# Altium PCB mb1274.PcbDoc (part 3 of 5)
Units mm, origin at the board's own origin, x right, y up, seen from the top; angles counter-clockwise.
Board outline 70 x 105 mm, 4 copper layers (Top Layer, Mid-Layer 1, Mid-Layer 2, Bottom Layer), stack 1.58 mm thick; 329 components, 271 nets, 1213 pads, 779 vias.
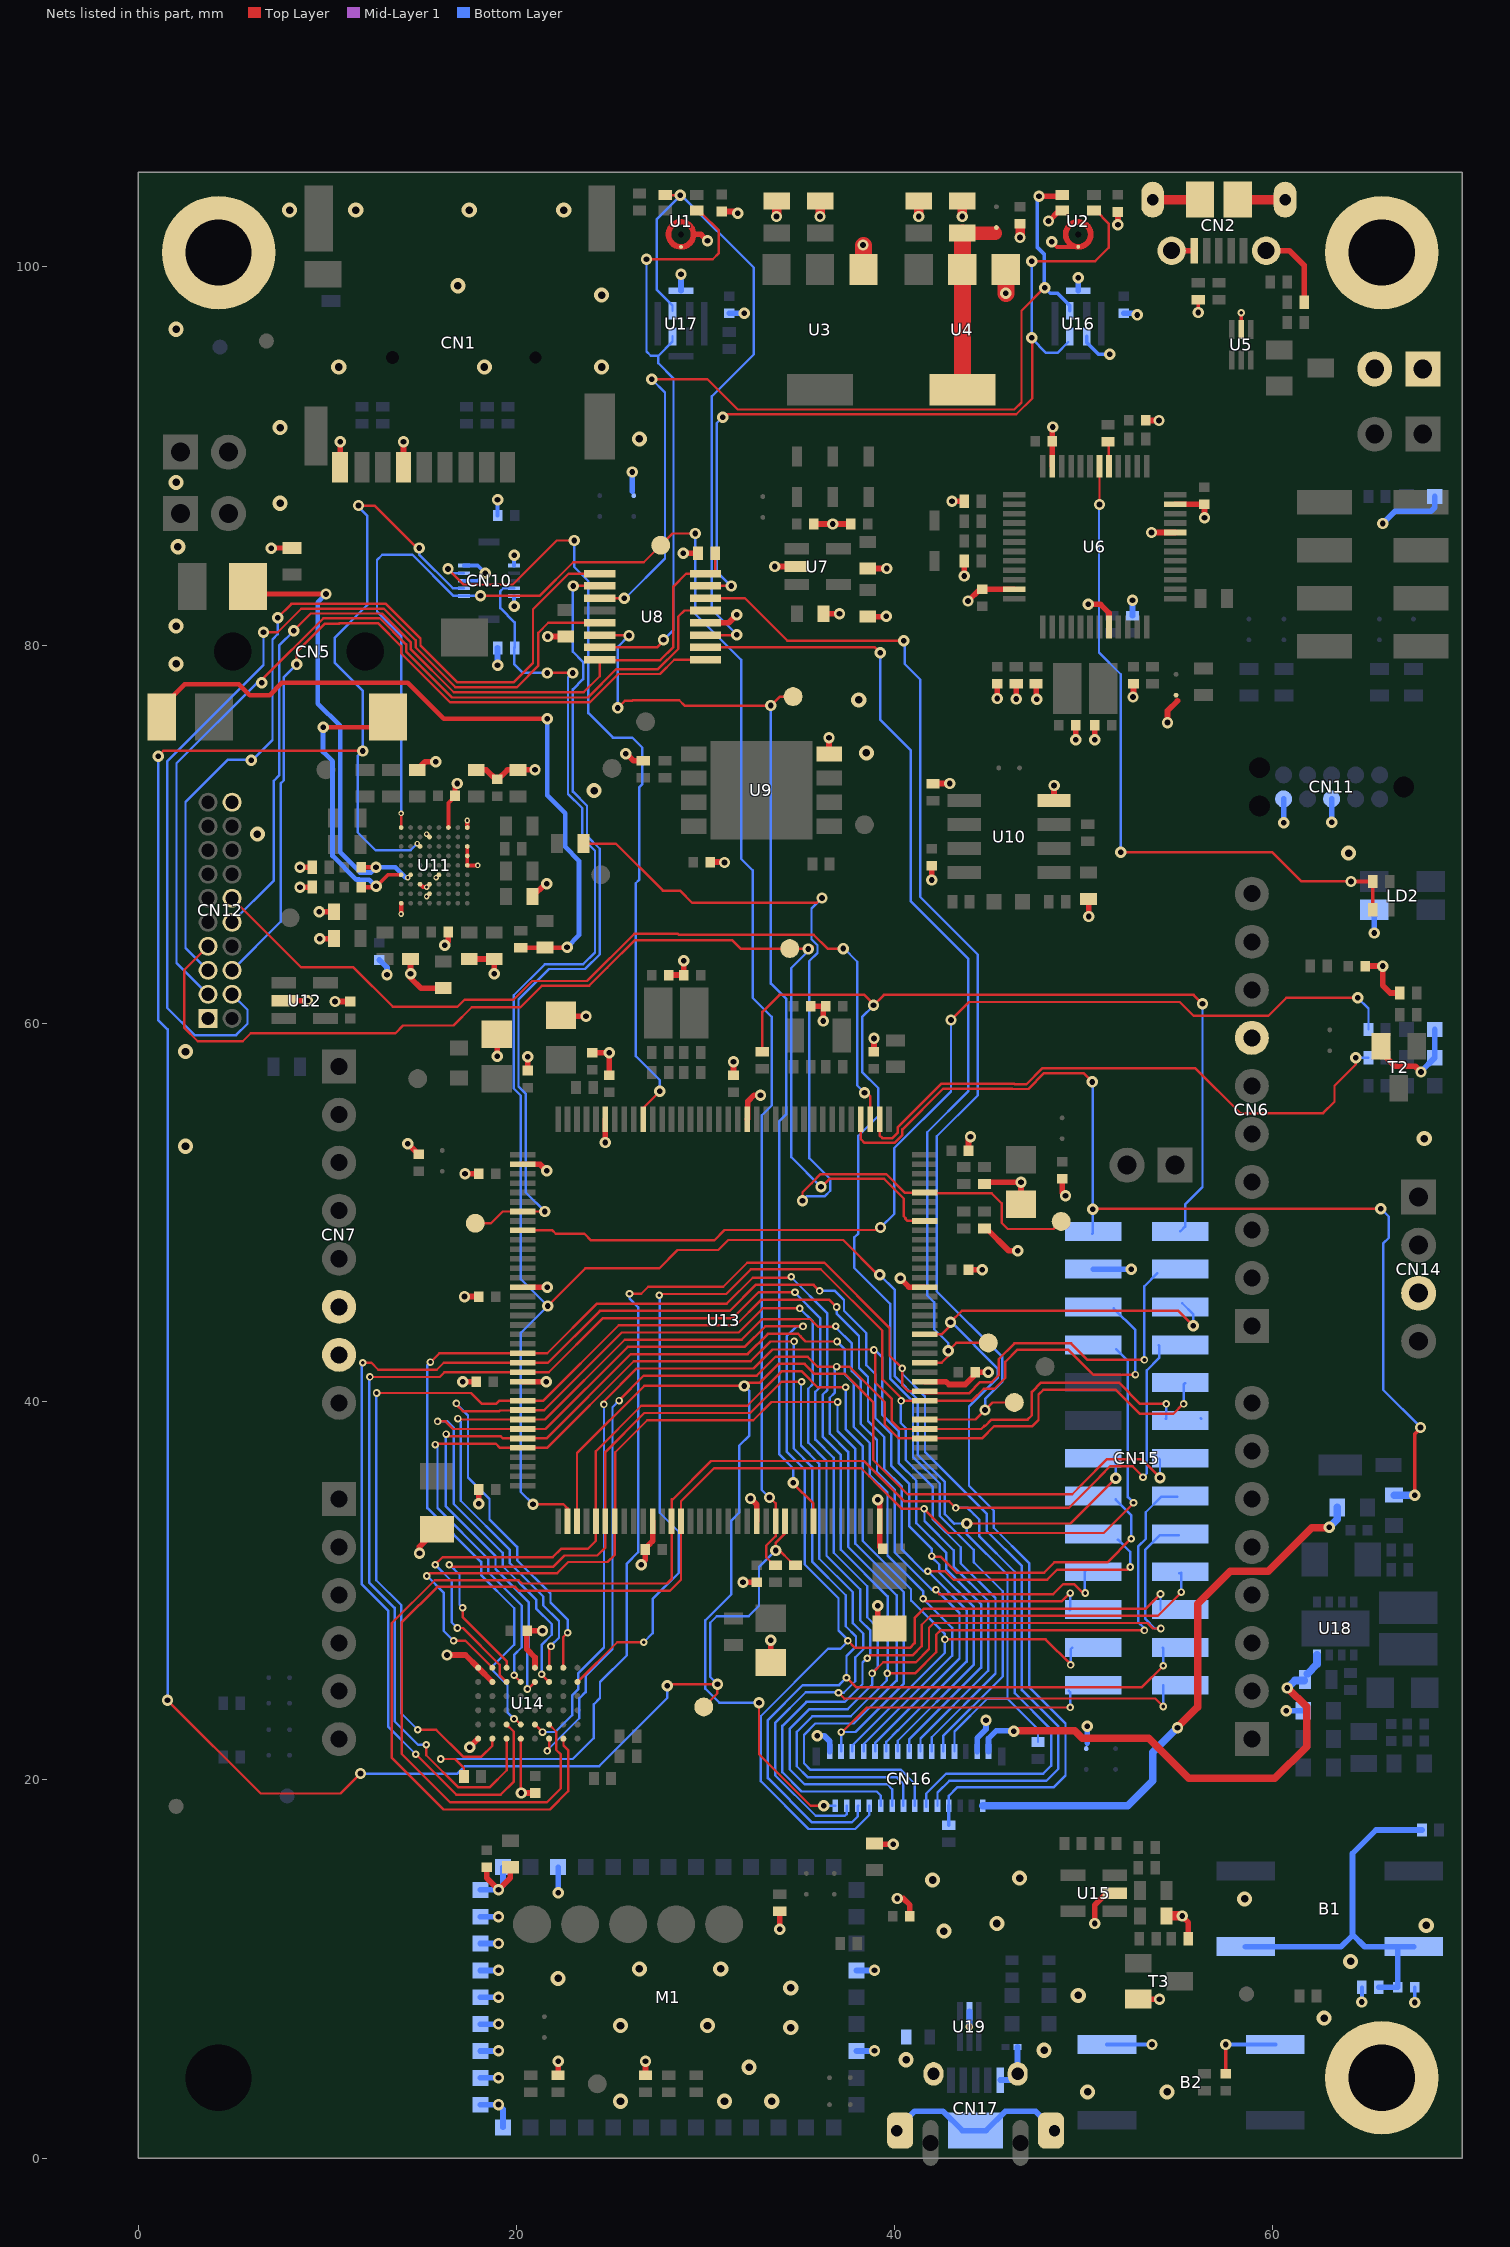
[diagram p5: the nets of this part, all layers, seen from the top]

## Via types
v1: diameter 0.6, hole 0.3, Top Layer to Bottom Layer, tented both sides, 574 vias
v2: diameter 0.4, hole 0.2, Top Layer to Bottom Layer, tented both sides, 125 vias
v3: diameter 0.8, hole 0.4, Top Layer to Bottom Layer, tented both sides, 49 vias
v4: diameter 0.3, hole 0.15, Top Layer to Bottom Layer, tented both sides, 31 vias

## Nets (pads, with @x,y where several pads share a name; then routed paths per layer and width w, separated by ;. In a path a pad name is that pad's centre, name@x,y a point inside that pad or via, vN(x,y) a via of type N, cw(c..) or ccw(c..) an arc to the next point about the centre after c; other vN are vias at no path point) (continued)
CODEC_WS: R28.1 TP11.1 U13.140 | length 48.8
  Top Layer w0.127: R28.1@23.55,69.5 25.25,69.5 27.738,67.012 28.644,67.012 29.279,66.377 35.877,66.377 v1@36.15,66.65 ; v1(35.125,50.625) v1@35.137,50.637 ; v1@35.125,50.65 35.125,51.064 35.609,51.549 35.609,51.553 36.08,52.024 39.548,52.024 40.522,51.05 U13.140@41.575,51.05 41.575,51.01 45.125,51.01 45.65,50.484 45.65,49.45 45.975,49.125 48.4,49.125 TP11.1@48.8,49.525
  Bottom Layer w0.127: v1@35.3,50.625 v1(35.125,50.625) 35.36,50.859 36.303,50.859 36.59,51.147 36.59,51.76 35.481,52.869 35.481,63.287 35.915,63.722 35.915,64.128 35.6,64.444 35.6,66.075 v1(36.15,66.625)
CTP_INT: CN10.2 U13.27 | length 42.6
  Top Layer w0.127: v1(16.375,84.025) 17.2,83.2 19.8,83.2 22.125,85.525 v1(23.05,85.525) ; U13.27@26.7,54.925 26.7,55.525 v1(27.575,56.4)
  Bottom Layer w0.127: v1(16.375,84.025) 16.6,83.8 CN10.2@17.225,83.8 ; v1(23.05,85.525) 23.05,84.125 23.8,83.375 23.8,76.4 25.096,75.104 26.121,75.104 26.654,74.571 26.654,72.645 26.5,72.491 26.5,67.575 ; 26.475,67.575 26.308,67.408 26.308,58.267 27.575,57 v1(27.575,56.4)
DETECTN: CN12.10 R13.2 U8.8 U8.16 | length 46.8
  Top Layer w0.127: v1(8.225,80.75) 8.225,80.767 9.125,81.667 12.89,81.667 14.417,80.14 14.417,79.765 16.682,77.5 23.55,77.5 24.4,78.35 U8.16@24.4,79.225 ; U8.16@24.525,79.2 27.6,79.2 28.296,79.896 28.296,83.096 28.975,83.775 U8.8@30,83.775 ; U8.8@30.45,83.775 30.5,83.825 R13.2@30.5,84.85
  Bottom Layer w0.127: CN12.10@4.96,65.34 7.175,67.555 7.175,72.825 7.45,73.1 7.45,79.975 v1(8.225,80.75)
DFSDM1_CKOUT: TP2.1 U8.14 U13.100 | length 59.7
  Top Layer w0.127: U8.14@24.4,80.525 25.925,80.525 v1(25.95,80.5) ; v1(25.35,76.675) 25.725,77.05 26.116,77.05 26.145,77.079 28.605,77.079 28.884,76.8 v1(33.45,76.8) 33.925,77.275 TP2.1@34.625,77.275 ; v1@34.625,35.675 35.7,34.6 U13.100@35.7,33.675
  Bottom Layer w0.127: v1(25.35,76.675) 25.35,79.9 v1(25.95,80.5) ; v1@33.45,76.75 33.45,62.1 34.271,61.279 34.271,55.196 33.9,54.825 33.9,37.2 34.625,36.475 v1(34.625,35.7)
DFSDM1_DATIN1: TP13.1 U8.2 U13.122 | length 53.8
  Top Layer w0.127: U8.2@30,79.875 38.95,79.875 v1(39.225,79.6) ; U13.122@41.575,42.05 42.3,42.05 42.475,42.05 42.827,42.402 v1(42.827,42.677) 43.25,43.1 TP13.1@44.95,43.1
  Bottom Layer w0.127: v1(39.225,79.6) 39.225,76.067 40.842,74.45 40.842,66.465 43.88,63.427 43.88,56.398 41.717,54.235 41.717,45.615 42.091,45.24 42.091,43.824 42.827,43.089 v1(42.827,42.677) 42.925,42.579 42.925,42.55 v1@42.813,42.662
DFSDM2_CKOUT: TP15.1 U8.6 U13.116 | length 61.6
  Top Layer w0.127: U8.6@30,82.475 32.075,82.475 34.326,80.225 v1(40.475,80.225) ; U13.116@41.575,39.05 44.275,39.05 v1(44.775,39.55) 45.175,39.95 TP15.1@46.325,39.95
  Bottom Layer w0.127: v1(40.475,80.225) 40.525,80.225 40.525,79 41.35,78.175 41.35,66.675 44.388,63.637 44.388,56.188 42.225,54.025 42.225,45.825 45.694,42.356 45.694,41.051 44.775,40.132 v1(44.775,39.55)
DFSDM2_DATIN1: TP12.1 U8.10 U13.43 | length 42.9
  Top Layer w0.127: TP12.1@17.825,49.425 18.65,49.425 19.275,50.05 U13.43@20.325,50.05 v1(21.5,50.05) ; v1(23,83.125) U8.10@24.4,83.125
  Bottom Layer w0.127: v1(21.5,50.05) 20.483,51.067 20.483,56.285 20.108,56.66 20.108,61.258 21.721,62.871 23.63,62.871 24.404,63.645 24.404,69.23 23.729,69.905 23.729,71.5 22.979,72.25 22.979,77.654 23.525,78.2 23.525,79.1 22.975,79.65 v1@22.975,83.1
DFSDM2_DATIN7: CN12.7 TP9.1 U13.137 | length 61.5
  Top Layer w0.127: CN12.7@3.69,64.07 2.425,62.805 2.425,59.775 3.15,59.05 5.525,59.05 5.95,59.475 13.6,59.475 14.008,59.883 16.665,59.883 17.632,60.85 20.207,60.85 21.34,61.983 23.842,61.983 24.801,62.942 ; 24.808,62.942 24.801,62.942 ; v1(35.425,63.925) 35.4,63.95 TP9.1@34.45,63.95 31.85,63.95 31.417,64.383 26.242,64.383 24.801,62.942 ; v1@35.425,63.95 35.575,63.95 v1@35.675,64.05 ; v1@36.125,51.35 36.545,51.77 39.443,51.77 40.475,50.738 40.475,49.8 40.575,49.7 ; 40.55,49.675 40.675,49.55 U13.137@41.575,49.55
  Bottom Layer w0.127: v1(35.425,63.925) 35.425,63.825 34.525,62.925 34.525,52.925 v1(36.1,51.35)
DMIC1_DFSDM1_CKOUT: U1.4 U8.15 U17.3 | length 32.8
  Top Layer w0.127: U8.15@24.4,79.875 27.425,79.875 27.775,80.225 v1(27.775,80.275) ; v1(26.875,100.4) 30.375,100.4 30.7,100.725 30.7,101.925 U1.4@29.825,102.8 ; U1.4@29.538,102.967 U1.4@29.765,102.74
  Bottom Layer w0.127: v1(26.875,100.4) 26.875,95.525 27.1,95.3 27.5,95.3 ; v1(27.775,80.275) 28.3,80.8 28.3,94.1 27.5,94.9 27.5,95.3 ; U17.3@28.25,96.325 28.25,96.05 27.5,95.3
DMIC1_DFSDM1_DATIN1: U1.1 U8.3 U17.4 | length 35.7
  Top Layer w0.127: U1.1@27.862,103.789 28.636,103.789 v1(28.65,103.775) ; U8.3@30,80.525 31.625,80.525 v1(31.65,80.55)
  Bottom Layer w0.127: U17.4@28.25,97.675 28.25,97.95 27.425,98.775 27.425,102.525 v1@28.675,103.775 ; v1@28.725,103.775 32.55,99.95 32.55,95.375 30.325,93.15 30.325,81.875 v1(31.65,80.55)
DMIC2_DFSDM2_CKOUT: U2.4 U8.7 U16.3 | length 44
  Top Layer w0.127: U8.7@30,83.125 v1(31.35,83.125) ; v1@30.925,92.025 31.1,92.2 46.427,92.2 47.275,93.048 v1@47.275,96.2 ; v1(47.25,100.3) 50.6,100.3 51.31,101.01 51.31,102.29 50.633,102.967 U2.4@50.538,102.967
  Bottom Layer w0.12: 48,95.45 48.6,95.45
  Bottom Layer w0.127: v1(30.9,92.05) 30.579,91.729 30.579,83.896 v1(31.35,83.125) ; v1@30.912,92.037 v1@30.95,92.075 ; v1(47.25,100.3) v1(47.25,96.25) 47.25,96.2 48,95.45 ; 48.6,95.45 U16.3@49.175,96.025
DMIC2_DFSDM2_DATIN1: U2.1 U8.11 U16.4 | length 49.4
  Top Layer w0.127: U8.11@24.4,82.475 v1@25.7,82.475 ; v1(27.15,94.05) 30.1,94.05 31.696,92.454 46.322,92.454 46.7,92.832 46.7,97.675 v1@47.9,98.875 ; v1@47.913,98.862 47.925,98.875 v1(47.925,98.9)
  Top Layer w0.3: v1(47.627,103.73) 47.632,103.725 48.798,103.725 U2.1@48.862,103.789
  Bottom Layer w0.127: v1(25.7,82.475) 25.75,82.475 27.85,84.575 27.85,93.35 v1(27.15,94.05)
  Bottom Layer w0.2: v1@47.53,103.73 47.53,101.045 47.9,100.675 47.9,98.925 v1(47.925,98.9) 48.225,98.6 48.6,98.6 49.25,97.95 U16.4@49.25,97.675
  Bottom Layer w0.3: v1@47.53,103.73 v1(47.627,103.73)
EXT_DFSDM1_CKOUT: CN12.4 U8.13 | length 51.6
  Top Layer w0.127: v1(6.625,80.675) 7.375,80.675 8.621,81.921 12.995,81.921 14.671,80.245 14.671,79.87 16.77,77.771 20.021,77.771 21.16,78.909 21.16,80.653 21.681,81.175 U8.13@24.4,81.175
  Bottom Layer w0.127: CN12.4@4.96,61.53 5.775,60.715 5.775,59.975 5.175,59.375 2.975,59.375 1.525,60.825 1.525,73.85 6.625,78.95 v1(6.625,80.675)
EXT_DFSDM1_DATIN1: CN12.6 U8.1 | length 43.4
  Top Layer w0.127: v1(8.375,78.975) 8.375,79.641 9.851,81.116 10.607,81.116 10.65,81.159 12.679,81.159 13.909,79.929 13.909,79.554 16.492,76.971 23.88,76.971 25.38,78.471 27.589,78.471 28.343,79.225 U8.1@30,79.225
  Bottom Layer w0.127: CN12.6@4.96,62.8 7.525,65.365 7.525,72.675 7.704,72.854 7.704,78.304 v1(8.375,78.975)
EXT_DFSDM2_CKOUT: CN12.3 U8.5 | length 49
  Top Layer w0.127: v1(6.525,78) 6.525,78.15 9.788,81.413 12.784,81.413 14.163,80.034 14.163,79.659 16.597,77.225 23.775,77.225 25.275,78.725 27.484,78.725 28.55,79.791 28.55,81.5 28.875,81.825 U8.5@30,81.825
  Bottom Layer w0.127: CN12.3@3.69,61.53 2.025,63.195 2.025,73.75 6.275,78 v1(6.525,78)
EXT_DFSDM2_DATIN1: CN12.5 U8.9 | length 45.2
  Top Layer w0.127: v1(7.375,81.45) 8.1,82.175 13.1,82.175 14.925,80.35 14.925,79.975 16.875,78.025 19.85,78.025 20.875,79.05 20.875,81.891 22.759,83.775 U8.9@24.4,83.775
  Bottom Layer w0.127: CN12.5@3.69,62.8 2.5,63.99 2.5,71.7 4.725,73.925 5.95,73.925 v1(5.975,73.9) ; v1@6.05,73.925 7.1,74.975 7.1,80.3 7.375,80.575 v1(7.375,81.45)
GND: B2.3 B2.4 C1.1 C2.1 C3.1 C4.1 C5.1 C6.1 C7.1 C8.1 C9.1 C10.1 C11.1 C12.1 C13.1 C14.1 C15.1 C16.1 C17.1 C18.1 C19.1 C20.2 C21.2 C22.1 C23.1 C24.1 C25.1 C26.1 C27.1 C28.1 C30.1 C32.1 C33.2 C35.1 C37.1 C38.1 C39.1 C40.2 C41.1 C42.1 C43.2 C44.2 C45.1 C46.2 C47.2 C48.2 C49.2 C50.1 C51.1 C52.1 C53.1 C54.1 C55.2 C56.1 C57.1 C58.1 C59.1 C60.1 C61.1 C62.1 C63.1 C64.1 C65.1 C66.1 C67.1 C68.1 C69.1 C70.2 C71.1 C72.1 C73.2 C74.2 C75.1 C76.1 C77.2 C78.1 C79.1 C80.1 C81.2 C82.1 C90.1 CN1.6 CN1.9 CN2.5 CN2.6 CN2.7 CN2.8 CN2.9 CN2.10 CN2.11 CN6.7 CN7.6 CN7.7 CN10.1 CN10.3 CN10.6 CN10.10 CN11.3 CN11.5 CN12.1 CN12.20 CN14.3 CN15.4 CN16.1 CN16.27 CN17.5 CN17.6 CN17.7 CN17.8 CN17.9 CN17.10 H1.1 H2.1 H4.1 JP1.1 JP1.2 L5.1 LD2.1 LD3.2 LD4.2 LD6.2 M1.1 M1.3 M1.17 M1.20 M1.35 M1.36 M1.37 M1.38 M1.39 M1.40 M1.41 M1.42 M1.43 M1.44 R3.1 R5.1 R9.1 R12.2 R13.1 R14.1 R16.2 R17.2 R20.2 R24.1 R32.1 R35.1 R41.1 R53.1 R55.1 R68.1 R70.1 R75.2 R76.2 R86.1 R88.1 R109.1 SB3.1 SB13.1 SB23.1 T2.2 T3.2 U1.3 U2.2 U2.3 U3.1 U4.1 U5.2 U6.8 U6.20 U6.23 U6.35 U6.47 U7.2 U8.4 U9.4 U10.4 U11.A1 U11.A3 U11.A4 U11.A5 U11.C1 U11.D6 U11.E2 U11.E7 U11.E8 U11.F7 U11.H9 U12.2 U13.16 U13.31 U13.38 U13.51 U13.61 U13.83 U13.94 U13.107 U13.120 U13.130 U14.D1 U14.E6 U14.G2 U14.H1 U14.H6 U15.2 U16.2 U16.5 U17.5 U19.2 U20.2 U21.2 | length 226
  Top Layer w0.127: v4(15.75,67.7) U11.D6@15.895,67.845 ; v4@15.766,67.715 v4@15.777,67.726 ; v4@15.766,67.716 U11.D6@15.9,67.85 ; v1@20.225,19.35 U14.E6@20.225,22.175 ; v1(33.918,12.095) v1@33.925,12.102 ; v1@39.822,16.6 v1(39.925,16.6)
  Top Layer w0.2: U11.F7@14.9,67.35 15.05,67.2 v4(15.25,67.2) U11.E7@15.4,67.35 ; v4(15.25,66.7) U11.E8@15.4,66.85 ; v4(15.25,70) U11.E2@15.4,69.85 ; U11.C1@16.4,70.35 16.4,71.65 C26.1@16.75,72 ; U11.A3@17.4,69.35 U11.A4@17.4,68.85 U11.A5@17.4,68.35 v4(17.95,68.35) ; v1(48.3,101.325) 48.573,101.052 U2.3@49.7,101.052 ; R3.1@56.05,98.25 56.05,97.582 v1(56.053,97.58) ; C78.1@57.5,4.45 v1(57.5,6) ; U5.2@58.325,96.68 v2(58.325,97.575)
  Top Layer w0.25: v1(7.025,85.125) R12.2@8.125,85.125 ; v4(13.9,65.775) U11.H9@13.9,66.35 ; C26.1@16.75,72.025 16.75,72.6 16.829,72.679 v1(16.876,72.679) ; U11.A1@17.4,70.35 v4(17.4,70.725)
  Top Layer w0.3: U12.2@7.7,61.2 v1(8.95,61.2) ; v1(8.55,67.2) R35.1@9.2,67.2 ; v1(8.55,68.25) R32.1@9.2,68.25 ; v1(9.575,65.9) C33.2@10.35,65.9 ; v1(9.6,64.475) C40.2@10.35,64.475 ; v1(10.4,61.15) C45.1@11.2,61.15 ; CN1.9@10.675,89.4 v1(10.675,90.75) ; CN1.6@14.025,89.4 v1(14.025,90.75) ; v1@14.3,53.6 C57.1@14.825,53.075 ; C37.1@14.4,63.4 v1(14.4,62.625) 14.4,62.4 14.95,61.85 15.925,61.85 15.95,61.875 C41.1@16.125,61.875 ; C22.1@14.75,73.4 15.175,73.825 v1@15.7,73.825 ; v1(14.875,31.975) 14.875,32.325 C64.1@15.8,33.25 ; v1(16.2,64.125) 16.4,64.325 C35.1@16.4,64.825 ; v1(16.325,26.6) 17.3,26.6 U14.H1@17.975,25.925 U14.G2@18.725,25.175 ; v1(17.15,41.05) C63.1@17.875,41.05 ; v1(17.25,45.55) C61.1@18,45.55 ; v1(17.275,52.05) C59.1@18,52.05 ; C38.1@17.5,63.4 C39.1@18.825,63.4 ; v1(17.525,21.725) U14.H6@17.975,22.175 ; C23.1@17.875,73.4 18.4,73.4 C25.1@18.9,72.9 ; v1(18,34.6) C65.1@18,35.35 ; C75.1@18.425,15.375 18.425,14.807 v1(19.045,14.187) 19.675,14.817 C73.2@19.675,15.375 ; v1(18.825,62.625) C39.1@18.825,63.4 ; C39.1@18.85,63.375 C39.1@18.825,63.4 ; C49.2@18.95,59.425 18.975,59.4 v1(18.975,58.25) ; C25.1@18.975,72.9 19.025,72.9 19.525,73.4 C24.1@20.075,73.4 v1(20.975,73.4) ; v1@20.225,19.35 v1@20.275,19.3 ; v1(20.25,19.3) v1@20.275,19.3 ; U13.61@20.325,41.05 v1(21.575,41.05) ; U13.51@20.325,46.05 v1(21.625,46.05) ; U13.38@20.325,52.55 21.25,52.55 v1(21.6,52.2) ; C71.1@20.55,27.85 20.55,26.9 20.975,26.475 U14.D1@20.975,25.925 ; C71.1@20.575,27.875 v1(21.375,27.875) ; C52.1@20.6,57.5 v1(20.6,58.225) ; C32.1@20.85,66.7 21.525,67.375 v1(21.6,67.375) ; C72.1@21,19.3 v1@20.275,19.3 ; v1(21.65,80.45) C16.1@22.6,80.45 ; R75.2@22.2,4.375 v1(22.2,5.125) ; C48.2@22.35,60.425 22.4,60.375 v1(23.675,60.375) ; C51.1@24,58.45 v1(24.9,58.45) ; v1(24.7,53.7) U13.31@24.7,54.925 ; v1@24.875,58.4 24.9,58.375 C53.1@24.9,57.25 ; v1(25.775,74.25) 25.85,74.25 25.837,74.238 26.2,73.875 R20.2@26.7,73.875 ; v1@26.675,31.5 26.8,31.625 C67.1@26.8,32.175 26.8,32.234 27.2,32.634 27.2,32.8 ; R76.2@26.825,4.375 v1(26.825,5.125) ; C67.1@27,32.425 27.2,32.625 U13.83@27.2,33.675 ; C43.2@28.05,62.55 28.825,62.55 C44.2@28.85,62.525 ; v1(28.825,84.85) R13.1@29.6,84.85 ; C44.2@28.85,62.55 v1(28.85,63.3) ; 29.363,101.715 29.76,101.715 v1(30.1,101.375) ; U8.4@30,81.175 31.225,81.175 v1(31.65,81.6) ; C28.1@30.25,68.525 31,68.525 v1(31,68.5) ; C1.1@30.85,102.925 31.7,102.925 v1(31.7,102.825) ; C54.1@31.475,57.25 v1(31.475,57.975) ; v1(31.975,30.45) C68.1@32.7,30.45 ; U13.16@32.2,54.925 32.232,54.957 32.232,55.877 32.558,56.202 v1(32.902,56.202) ; v1(32.375,34.875) 32.7,34.55 U13.94@32.7,33.675 ; C70.2@33.45,26.2 33.45,27.374 v1(33.452,27.376) ; v1(33.65,84.15) U7.2@34.825,84.15 ; v1@33.75,102.657 v1(33.752,102.655) ; v1@33.925,12.102 R68.1@33.925,13.05 ; C46.2@35.55,60.9 36.275,60.9 C47.2@36.3,60.925 ; C11.1@35.725,86.4 36.675,86.4 v1@36.7,86.425 ; v1@36.05,102.657 v1(36.052,102.655) ; v1(36.225,60.125) 36.225,60.775 C47.2@36.35,60.9 ; C17.1@36.225,81.65 v1(37.075,81.65) ; U9.4@36.525,74.23 v1(36.525,75.1) ; v1(36.725,86.4) C12.1@37.675,86.4 ; v1(38.325,101.15) v1@38.35,101.125 ; C14.1@38.575,81.5 39.525,81.5 v1(39.55,81.525) ; C13.1@38.575,84.05 v1(39.575,84.05) ; C74.2@38.874,16.6 v1@39.822,16.6 ; C50.1@38.9,58.5 v1(38.9,59.2) ; v1(39.1,29.2) 39.1,28.625 C69.1@39.725,28 ; v1(39.1,34.8) 39.2,34.7 U13.107@39.2,33.675 39.2,32.325 C66.1@39.275,32.25 ; v1(40.125,13.725) 40.45,13.725 40.8,13.375 C77.2@40.8,12.775 ; v1(40.3,46.525) 40.275,46.525 40.75,46.05 U13.130@41.575,46.05 ; v1@41.275,102.65 41.277,102.652 v1(41.277,102.655) ; U13.120@41.575,41.05 42.711,41.05 42.863,40.899 43.725,40.899 44.175,41.349 C62.1@44.175,41.375 ; v1(41.95,67.575) C27.1@41.95,68.325 ; R24.1@42.025,72.675 v1(42.9,72.675) ; v1(43.025,87.6) R9.1@43.675,87.6 ; v1@43.575,102.65 v1(43.577,102.655) v1(43.577,102.655) ; v1(43.675,83.65) R14.1@43.675,84.45 ; v1(43.875,82.325) 44.5,82.95 C15.1@44.625,82.95 ; C60.1@43.9,46.975 v1(44.625,46.975) ; C56.1@43.9,53.25 43.9,53.95 43.952,54.002 v1(44.002,54.002) ; C62.1@44.25,41.55 v1(44.95,41.55) ; C15.1@44.6,82.925 C15.1@44.625,82.95 ; R55.1@44.75,49.15 44.85,49.15 46.025,47.975 v1(46.5,47.975) ; R53.1@44.75,51.5 44.85,51.6 v1@46.675,51.6 ; v1(45.425,77.175) C19.1@45.425,77.95 ; U6.47@46.325,82.95 C15.1@44.625,82.95 ; v1(46.425,77.15) R16.2@46.425,77.95 ; C55.2@46.675,50.425 v1@46.675,51.6 ; v1(46.677,51.602) v1@46.675,51.6 ; R17.2@47.475,77.95 47.475,77.15 v1(47.5,77.125) ; v1@48.125,102.4 48.692,102.967 U2.2@48.862,102.967 ; U6.35@48.325,89.45 48.325,90.725 C9.1@48.35,90.75 ; C9.1@48.325,90.775 48.325,91.5 v1(48.35,91.525) ; U10.4@48.425,71.78 v1(48.425,72.575) ; C58.1@48.85,51.775 48.85,51.025 49,50.875 v1(49.025,50.875) ; v1(49.575,75) C20.2@49.575,75.75 ; v1(50.225,82.15) 50.875,82.15 51.325,81.7 U6.8@51.325,80.95 ; v1(50.25,65.65) C30.1@50.25,66.575 ; v1(50.575,12.4) 50.575,13.35 ; 50.575,13.375 51.2,14 U15.2@51.625,14 ; v1(50.575,75) C21.2@50.575,75.75 ; U15.2@51.133,13.9 U15.2@51.15,13.9 ; v1(51.8,102.225) C2.1@51.8,102.9 ; v1(52.6,77.25) 52.625,77.225 C18.1@52.625,77.95 ; v1(52.828,97.455) v1@52.828,97.553 ; T3.2@52.875,8.4 v1(54,8.4) ; C8.1@53.275,91.875 v1(53.975,91.875) ; v1(53.575,85.95) U6.20@54.825,85.95 ; v1(54.425,75.9) 54.425,76.525 54.95,77.05 ; CN2.7@54.475,100.9 54.525,100.85 CN2.7@54.64,100.85 CN2.5@55.84,100.85 ; U6.23@54.825,87.45 56.35,87.45 C10.1@56.375,87.475 ; v1@55.2,12.775 55.525,12.45 R70.1@55.525,11.6 ; v1(56.375,86.725) C10.1@56.375,87.45 ; CN2.6@59.675,100.85 60.875,100.85 61.65,100.075 R5.1@61.65,98.125 ; C42.1@64.875,63.025 v1(65.8,63.025) 65.8,62 66.2,61.6 R41.1@66.7,61.6 ; T2.2@65.7,58.775 65.7,58.475 66.45,57.725 67.525,57.725 v1(67.825,57.425)
  Top Layer w0.5: v1@33.75,102.657 C3.1@33.75,103.475 ; v1@36.05,102.657 C4.1@36.05,103.475 ; v1@41.275,102.65 C5.1@41.275,103.475 ; v1(43.577,102.655) C6.1@43.575,103.475 ; v1(46.625,101.55) C7.1@46.625,102.275 ; CN2.8@53.675,103.55 CN2.11@56.14,103.55 ; C76.1@54.375,12.8 v1(55.2,12.8) ; CN2.10@58.14,103.55 CN2.9@60.6,103.55
  Top Layer w0.9: U3.1@38.35,99.85 v1@38.35,101.125 ; v1(45.875,98.6) U4.1@45.875,99.85
  Mid-Layer 1 w0.127: v4@15.715,67.664 v4@15.777,67.726
  Mid-Layer 1 w0.3: v1@32.825,56.279 v1(32.902,56.202) ; v1@33.752,102.577 v1(33.752,102.655) ; v1@36.052,102.577 v1(36.052,102.655) ; v1@43.577,102.554 v1(43.577,102.655) ; v1(56.375,86.725) v1@56.4,86.7
  Bottom Layer w0.127: v1@19.038,2.82 v1(19.045,2.827) ; v1@19.038,4.24 v1(19.045,4.247) ; v1@19.038,5.66 v1(19.045,5.667) ; v1@19.038,7.08 v1(19.045,7.087) ; v1@19.038,8.5 v1(19.045,8.507) ; v1@19.038,9.92 v1(19.045,9.927) ; v1@19.038,11.34 v1(19.045,11.347) ; v1@19.038,12.76 v1(19.045,12.767) ; v1@19.038,14.18 v1(19.045,14.187) ; v1@38.922,5.66 v1(38.929,5.667) ; v1@38.922,9.92 v1(38.929,9.927)
  Bottom Layer w0.2: CN10.3@17.225,83.4 17.95,83.4 v1(18.35,83.8) 17.95,84.2 CN10.1@17.225,84.2 ; C81.2@19,86.85 v1(19,87.675) ; v1(19.875,82.05) CN10.6@19.875,82.6 ; CN10.10@19.875,84.2 v1(19.875,84.75) ; U16.2@50.15,96.325 50.15,96 50.775,95.375 v1(51.375,95.375) ; B2.3@51.225,6 v1(53.6,6) ; v1(57.5,6) B2.4@60.125,6 ; v1(64.7,8.25) R109.1@64.7,9.025 ; v1(67.5,8.225) C90.1@67.5,9.025
  Bottom Layer w0.3: C82.1@12.75,63.35 13.15,62.95 v1(13.15,62.575) ; M1.36@18.09,2.82 v1@19.038,2.82 ; M1.37@18.09,4.24 v1@19.038,4.24 ; M1.38@18.09,5.66 v1@19.038,5.66 ; M1.39@18.09,7.08 v1@19.038,7.08 ; M1.40@18.09,8.5 v1@19.038,8.5 ; M1.41@18.09,9.92 v1@19.038,9.92 ; M1.42@18.09,11.34 v1@19.038,11.34 ; M1.43@18.09,12.76 v1@19.038,12.76 ; M1.44@18.09,14.18 v1@19.038,14.18 ; v1(19,78.925) R88.1@19,79.85 ; v1(19.045,2.827) 19.29,2.582 M1.35@19.29,1.62 ; v1(19.045,14.187) 19.29,14.432 M1.1@19.29,15.38 ; v1(22.2,14.025) 22.204,14.029 M1.3@22.204,15.38 ; 26.125,88.125 v1(26.125,89.15) ; U17.5@28.7,98.725 v1(28.7,99.6) ; C80.1@31.25,97.55 v1(32.05,97.55) ; v1@35.9,22.3 v1@35.925,22.325 ; v1(35.9,22.325) v1@35.925,22.325 ; CN16.1@36.56,21.5 36.56,22.04 36.275,22.325 v1@35.925,22.325 ; M1.20@37.974,5.66 v1@38.922,5.66 ; M1.17@37.974,9.92 v1@38.922,9.92 ; CN17.9@40.1,1.525 41.05,2.475 42.55,2.475 43.575,1.45 44.825,1.45 45.85,2.475 47.45,2.475 CN17.8@48.425,1.5 ; v2(43.95,6.95) U19.2@43.95,7.755 ; CN16.27@44.36,21.5 44.36,22.21 44.825,22.675 v1(44.825,23.15) ; CN17.5@45.575,4.125 46.175,4.125 CN17.6@46.487,4.438 ; U20.2@46.487,5.875 CN17.6@46.487,4.438 ; CN17.6@46.5,4.35 46.487,4.363 CN17.6@46.487,4.438 ; CN17.6@46.5,4.45 CN17.6@46.487,4.438 ; U16.5@49.7,98.725 v1(49.7,99.425) ; 50.175,21.95 v1(50.175,22.825) ; CN15.4@50.5,47 v1(52.5,47) ; C79.1@52.1,97.55 52.8,97.55 52.828,97.522 v1(52.828,97.455) ; R86.1@52.575,81.55 v1(52.575,82.375) ; CN11.5@60.56,71.865 60.56,70.585 v1(60.575,70.6) ; v1(60.7,23.65) L5.1@61.6,23.65 ; v1(63.1,70.625) CN11.3@63.1,71.865 ; v1(65.35,64.775) LD2.1@65.35,65.975 ; v1(65.8,86.425) 66.45,87.075 68.35,87.075 68.55,87.275 LD6.2@68.55,87.85 ; v1(67.825,57.425) 67.825,57.45 LD4.2@68.55,58.175 LD3.2@68.55,59.675
  other v1: 26.6,31.375 14.25,53.625 15.725,73.825 48.133,102.417
  other v3: 25.5,3 31,3 33.5,3 50.2,3.5 54.4,3.5 32.3,4.8 40.6,5.2 47.9,5.7 34.5,6.9 25.5,7 30.1,7 62.7,7.4 49.7,8.6 34.5,9 22.2,9.5 26.5,10 30.8,10 64.1,10.4 42.6,12 68.1,12.3 45.4,12.4 58.5,13.7 42,14.7 46.6,14.8 2.5,53.5 68,53.9 2.5,58.5 64,69 6.3,70 24.1,72.3 38.5,74.3 38.1,77.1 2,79 2,81 2.1,85.2 7.5,87.5 2,88.6 26.5,90.9 7.5,91.5 10.6,94.7 18.3,94.7 24.5,94.7 2,96.7 24.5,98.5 16.9,99 8,103 11.5,103 17.5,103 22.5,103
HP_OUT_L: C31.2 CN5.6 U11.H6 | length 16
  Top Layer w0.2: v1@12.6,67.25 13.2,67.85 U11.H6@13.9,67.85
  Top Layer w0.25: v1(9.775,75.65) 12.65,75.65 CN5.6@13.2,76.2 ; C31.2@11.8,67.2 v1@12.575,67.2 ; v1@12.576,67.201 v1(12.576,67.253)
  Bottom Layer w0.25: v1(9.775,75.65) 9.775,74.35 10.275,73.85 10.275,68.85 11.527,67.598 11.675,67.598 ; 11.675,67.588 12.213,67.588 v1@12.6,67.2
HP_OUT_R: C29.2 CN5.4 U11.G6 | length 23.9
  Top Layer w0.127: v4(14.25,67.7) U11.G6@14.4,67.85
  Top Layer w0.25: CN5.4@5.8,83.1 6.2,82.7 v1(9.925,82.7) ; C29.2@11.8,68.25 v1(12.575,68.25)
  Bottom Layer w0.25: v1(9.925,82.7) 9.491,82.266 9.491,76.906 10.675,75.721 10.675,69.05 11.725,68 ; 11.725,67.975 12.325,67.975 v1@12.575,68.225 ; v1@12.6,68.25 13.6,68.25 14.15,67.7 v4(14.25,67.7)
I2CFMP1_SCL: CN10.5 R56.1 TP1.1 U11.H1 U13.96 | length 91.1
  Top Layer w0.127: U11.H1@13.9,70.35 v4(13.9,71.1) ; v1(18.1,82.6) 21.225,82.6 23,84.375 26.725,84.375 TP1.1@27.625,85.275 28.25,85.9 v1(29.45,85.9) ; v1@33.4,34.925 33.7,34.625 U13.96@33.7,33.675 33.7,32.875 33.21,32.385 33.21,31.765 R56.1@33.675,31.3
  Bottom Layer w0.127: v4(13.9,71.1) 13.9,80.5 12.625,81.775 12.625,84.5 12.9,84.775 14.5,84.775 16.675,82.6 CN10.5@17.225,82.6 v1(18.1,82.6) ; v1(29.45,85.9) 29.45,81.65 31.875,79.225 31.875,68.7 32.483,68.092 32.483,61.35 33.497,60.336 33.497,55.657 32.971,55.13 32.971,35.329 v1(33.375,34.925)
I2CFMP1_SDA: CN10.4 R57.1 TP16.1 U11.F3 U13.97 | length 138.9
  Top Layer w0.127: v1(1.05,74.125) 1.325,74.4 v1(11.875,74.4) ; v1(1.55,24.2) 6.475,19.275 10.7,19.275 v1(11.754,20.329) ; v1(11.65,87.375) 12.5,87.375 14.746,85.129 v1(14.851,85.129) ; v4(14.75,69.5) U11.F3@14.9,69.35 ; v1(27.975,24.975) 28.05,25.05 v1(30.625,25.05) 30.625,24.575 TP16.1@29.9,23.85 ; v1(33.7,32.125) 33.7,32.516 34.225,33.041 U13.97@34.225,33.4 ; v1@33.9,32.125 R57.1@34.5,31.525
  Mid-Layer 1 w0.127: v1@14.851,85.051 v1(14.851,85.129)
  Bottom Layer w0.127: v1(1.05,74.125) 1.05,60.175 1.55,59.675 v1(1.55,24.2) ; v1(11.65,87.375) 11.65,87.3 12.1,86.85 12.1,82.1 10.4,80.4 10.4,79.05 11.875,77.575 v1(11.875,74.4) 11.6,74.125 11.6,70.1 12.55,69.15 14.4,69.15 v4(14.75,69.5) ; v1(11.754,20.329) 16.879,20.329 17.275,20.725 24.375,20.725 27.975,24.325 v1(27.975,24.975) ; v1(14.851,85.129) 14.851,84.783 16.634,83 CN10.4@17.225,83 ; v1(30.625,25.05) 30.241,25.434 30.241,28.3 30.591,28.65 32.275,28.65 32.825,29.2 32.825,31.25 v1(33.7,32.125)
LCD-CTP_RST: CN10.7 CN15.14 CN16.23 R88.2 R103.2 U13.74 | length 123
  Top Layer w0.127: v1(20.875,34.575) 22.475,34.575 22.7,34.35 U13.74@22.7,33.675 ; v1(21.625,78.525) v1(22.975,78.525) ; v1(21.651,45.052) 23.645,47.046 27.555,47.046 28.522,48.013 30.666,48.013 31.195,48.542 37.278,48.542 39.12,46.7 v1@39.175,46.7 ; v1@39.2,46.675 v1@39.175,46.7 ; v1(39.2,46.7) v1@39.175,46.7 ; v1(43.8,33.55) 49.3,33.55 v1@51.675,35.925
  Bottom Layer w0.127: CN10.7@19.875,83 19.3,83 19.15,82.85 19.15,81.95 19.9,81.2 R88.2@19.9,79.85 19.875,79.875 19.875,79 20.35,78.525 v1(21.625,78.525) ; v1(20.875,34.575) 20.229,35.221 20.229,43.63 v1(21.651,45.052) 20.229,46.474 20.229,56.18 19.854,56.555 19.854,61.479 21.5,63.125 23.525,63.125 24.15,63.75 24.15,69.125 23.475,69.8 23.475,71.375 22.725,72.125 22.725,78.275 v1(22.975,78.525) ; v1@39.225,46.675 40.01,45.89 40.01,41.325 41.219,40.115 41.219,37.179 42.65,35.748 42.65,34.039 43.139,33.55 ; 43.145,33.545 43.139,33.55 ; CN16.23@43.16,21.5 43.16,22.554 44.895,24.289 45.962,24.289 ; v1@43.8,33.575 v1(43.8,33.55) ; R103.2@47.575,22 47.575,22.675 45.962,24.289 ; CN15.14@51.575,37.05 51.678,36.947 v1(51.678,35.952) ; 43.139,33.55 v1(43.8,33.55) ; v1(43.8,33.55) 43.8,33 45.962,30.839 45.962,24.289
LCD-PSRAM_D0: CN15.7 CN16.18 U13.85 U14.B6 | length 100.3
  Top Layer w0.127: U14.B6@22.475,22.175 U14.B6@22.487,22.163 ; U14.B6@22.487,22.175 U14.B6@22.487,22.163 ; 50.844,36.031 51.388,36.575 52.575,36.575 53.137,36.013 v2@53.15,36 ; 50.85,36.025 49.2,34.375 v2(43.225,34.375) 42.88,34.72 40.518,34.72 38.383,36.856 30.292,36.856 28.261,34.825 28.2,34.825 U13.85@28.2,33.675 28.2,31.55 28.2,30.619 27.961,30.38 20.286,30.38 20.116,30.55 15.675,30.55 13.4,28.275 13.4,21.175 16.146,18.429 21.767,18.429 22.731,19.392 22.731,21.569 22.487,21.813 U14.B6@22.487,22.163
  Bottom Layer w0.127: CN16.18@41.66,18.625 41.66,19.26 42.725,20.325 47.85,20.325 48.269,20.744 48.269,22.656 46.343,24.582 46.343,30.996 44.475,32.864 44.475,33.75 44.175,34.05 43.85,34.375 v2(43.225,34.375) ; CN16.18@41.675,18.575 CN16.18@41.675,18.625 ; v2(53.125,36) 53.325,36.2 53.325,41.65 53.975,42.3 53.975,42.95 CN15.7@53.95,42.975
LCD-PSRAM_D1: CN15.8 CN16.17 U13.86 U14.C5 | length 91.4
  Top Layer w0.127: U14.C5@21.725,22.925 22.106,22.544 22.106,21.583 22.35,21.339 ; 22.35,21.35 22.35,21.339 ; 38.65,36.05 39.149,35.55 ; 38.65,36.05 38.225,36.475 30.45,36.475 28.7,34.725 U13.86@28.7,33.675 28.7,30.58 28.119,29.999 20.129,29.999 19.925,30.203 15.819,30.203 13.925,28.309 13.925,21.375 16.49,18.81 21.61,18.81 22.35,19.55 22.35,21.339 ; 39.15,35.55 40.361,34.339 41.539,34.339 v2(41.552,34.327) 42.829,33.05 51.05,33.05 v2@52.625,34.625
  Bottom Layer w0.127: CN16.17@41.36,21.5 41.36,22.191 44.946,25.776 44.946,29.452 43.112,31.285 43.112,32.141 41.573,33.679 41.573,34.327 v2(41.552,34.327) ; CN15.8@51.7,42.775 52.325,42.15 52.325,34.95 v2(52.625,34.65)
LCD-PSRAM_D2: CN15.9 CN16.16 U13.114 U14.C6 | length 91.1
  Top Layer w0.127: v2(21.625,21.525) 21.725,21.525 U14.C6@21.725,22.175 ; v2@25.4,40.05 25.412,40.063 26.715,41.365 32.695,41.365 33.699,42.369 35.39,42.369 35.918,41.841 v2@36.925,41.841 ; v2@36.95,41.85 37.597,41.85 39.469,39.978 39.469,38.792 40.211,38.05 U13.114@41.575,38.05 44.614,38.05 45.264,38.7 47.275,38.7 47.6,39.025 47.6,40.369 47.85,40.619 51.692,40.619 52.961,39.35 54.725,39.35 v2@55.25,39.875 ; v2@55.263,39.863 v2(55.275,39.875)
  Bottom Layer w0.127: v2(21.625,21.525) 21.625,21.561 23.32,23.256 23.32,24.301 23.655,24.636 23.655,25.484 25.075,26.904 25.075,39.7 v2(25.425,40.05) ; v2(36.925,41.85) 36.818,41.743 36.818,40.452 36.567,40.201 36.567,38.305 37.536,37.336 37.536,32.322 40.1,29.758 40.1,25.244 37.831,22.975 35.8,22.975 35.2,22.375 35.2,20.875 35.55,20.525 40.325,20.525 41.06,19.79 CN16.16@41.06,18.625 ; v2(55.275,39.875) 55.275,40.9 CN15.9@55.35,40.975
LCD-PSRAM_D3: CN15.11 CN16.15 U13.115 U14.D5 | length 82.2
  Top Layer w0.127: U14.D5@20.975,22.925 v2(21.375,22.525) ; v2@24.625,39.875 24.625,40.017 26.354,41.746 32.537,41.746 33.541,42.75 v2@38.875,42.75 ; v2@38.925,42.725 38.963,42.687 38.963,41.023 39.85,40.136 39.85,38.95 40.25,38.55 U13.115@41.575,38.55 44.575,38.55 44.737,38.712 44.786,38.712 45.12,39.047 47.025,39.047 47.253,39.275 47.253,40.513 47.74,41 51.85,41 52.975,39.875 v2(54.35,39.875)
  Bottom Layer w0.127: v2(21.375,22.525) 22.05,22.525 22.939,23.414 22.939,24.459 23.274,24.794 23.274,25.641 24.625,26.992 v2(24.625,39.85) ; v2(38.9,42.725) 38.95,42.725 39.349,42.326 39.349,39.294 40.203,38.44 40.203,36.758 41.139,35.822 41.139,33.574 42.731,31.983 42.731,31.127 44.565,29.294 44.565,25.934 40.76,22.129 CN16.15@40.76,21.5 ; CN15.11@54.325,39.075 54.35,39.1 v2(54.35,39.875) ; CN15.11@56.175,39.125 CN15.11@56.2,39.1
LCD-PSRAM_D4: CN15.15 CN16.14 U13.58 U14.E5 | length 105.5
  Top Layer w0.127: v2(15.45,42.089) v2@15.475,42.089 ; v2@15.475,42.1 15.925,42.55 U13.58@20.325,42.55 21.625,42.55 24.25,45.175 31.116,45.175 32.488,46.547 34.496,46.547 34.538,46.588 v2@34.55,46.6 ; v2(19.869,23.22) 19.93,23.22 U14.E5@20.225,22.925 ; v2@39.575,25.625 v2(39.602,25.626) 41.066,25.625 42.193,26.752 42.193,27.675 42.418,27.9 v2(53.2,27.9)
  Mid-Layer 1 w0.127: v2(19.869,23.22) v2@19.869,23.281
  Bottom Layer w0.127: v2(15.45,42.089) 15.286,41.925 15.286,34.367 18.129,31.524 18.129,30.821 19.877,29.072 19.877,27.147 18.775,26.045 18.775,25.75 19.525,25 19.525,23.564 v2(19.869,23.22) ; v2@34.525,46.575 36.437,44.663 36.437,40.609 36.186,40.358 36.186,38.147 37.155,37.178 37.155,32.165 39.625,29.695 v2@39.625,25.65 ; v2(39.602,25.626) 39.584,25.608 39.584,25.266 37.673,23.356 35.642,23.356 34.819,22.533 34.819,20.717 35.392,20.144 40.1,20.144 40.46,19.784 CN16.14@40.46,18.625 ; v2(39.602,25.626) v2@39.625,25.625 ; v2(53.2,27.9) 53.2,28.011 52.869,28.342 52.869,32.333 53.275,32.739 53.275,34.15 54.1,34.975 CN15.15@54.95,34.975
  other v2: 34.525,46.6
LCD-PSRAM_D5: CN15.16 CN16.13 U13.59 U14.F5 | length 101.7
  Top Layer w0.127: v2(11.875,42.05) 12.325,42.05 12.694,41.681 15.781,41.681 16.15,42.05 U13.59@20.325,42.05 21.664,42.05 24.408,44.794 31.274,44.794 32.646,46.166 35.709,46.166 v2(36.025,45.85) ; v2(14.675,21.35) 14.685,21.35 16.816,19.219 19.169,19.219 19.862,19.912 19.862,22.538 U14.F5@19.475,22.925 ; v2(41.952,31.827) 41.975,31.804 42.424,31.804 43.27,30.957 47.902,30.957 48.437,31.493 51.243,31.493 v2(52.5,32.75)
  Bottom Layer w0.127: v2(11.875,42.05) 11.825,42.05 11.825,30.331 13.209,28.947 13.209,22.816 v2(14.675,21.35) ; v2(36.025,45.85) 36.843,45.85 37.316,45.377 37.316,44.798 38.493,43.621 38.493,41.923 38.968,41.448 38.968,39.137 39.822,38.283 39.822,36.6 40.758,35.664 40.758,33.417 41.95,32.225 41.95,31.827 v2@41.95,31.775 ; CN16.13@40.16,21.5 40.16,22.068 44.184,26.092 44.184,29.136 42.35,30.97 42.35,31.375 v2@41.95,31.775 ; v2(41.952,31.827) 41.952,31.777 v2@41.95,31.775 ; CN15.16@51.675,34.825 52.5,34 v2(52.5,32.75)
LCD-PSRAM_D6: CN15.17 CN16.12 U13.60 U14.F6 | length 113.9
  Top Layer w0.127: v2(12.251,41.302) 15.939,41.3 16.189,41.55 U13.60@20.325,41.55 21.703,41.55 24.566,44.413 31.432,44.413 32.794,45.775 v2(34.725,45.775) ; v2(15.225,21.85) 15.225,21.301 16.926,19.6 18.575,19.6 19.481,20.506 U14.F6@19.481,22.169 ; U14.F6@19.475,22.175 U14.F6@19.481,22.169 ; U14.F6@19.481,22.175 U14.F6@19.481,22.169 ; v2(38.802,25.626) 39.389,26.213 41.116,26.213 41.812,26.909 41.812,28.037 42.065,28.29 53.362,28.29 53.652,28 v2(54.075,28)
  Bottom Layer w0.127: v2(12.251,41.302) 12.206,41.257 12.206,30.44 13.556,29.09 13.556,23.094 14.8,21.85 v2(15.225,21.85) ; v2(34.725,45.775) 34.725,45.75 36.056,44.419 36.056,40.767 35.805,40.516 35.805,37.989 36.774,37.02 36.774,32.007 38.55,30.231 38.55,28.591 39.093,28.048 39.093,25.943 v2@38.8,25.65 ; v2(38.802,25.626) 38.802,25.024 37.515,23.737 35.484,23.737 34.438,22.691 34.438,20.559 35.234,19.763 39.6,19.763 39.86,19.503 CN16.12@39.86,18.625 ; v2(54.075,28) 53.75,28 53.25,28.5 53.25,32.175 54,32.925 CN15.17@55.025,32.925
LCD-PSRAM_D7: CN15.18 CN16.11 U13.63 U14.G6 | length 92
  Top Layer w0.127: v2(12.601,40.451) 12.618,40.451 12.619,40.45 17.6,40.45 18.175,39.875 18.92,39.875 19.095,40.05 U13.63@20.325,40.05 21.425,40.05 25.407,44.032 31.59,44.032 32.932,45.374 35.7,45.374 36.55,45.375 v2(36.925,45) ; v2(14.775,22.65) 15.75,22.65 17.175,21.225 18.15,21.225 18.725,21.8 U14.G6@18.725,22.175 ; v2@41.75,31.025 42.664,31.025 43.112,30.576 48.059,30.576 48.595,31.112 49.791,31.112 49.797,31.106 52.306,31.106 v2(52.45,31.25)
  Bottom Layer w0.127: v2(12.601,40.451) 12.587,40.438 12.587,30.55 13.903,29.234 13.903,23.522 v2(14.775,22.65) ; v2(36.925,45) 36.925,44.65 38.112,43.463 38.112,41.766 38.587,41.291 38.587,38.979 39.441,38.125 39.441,36.443 40.377,35.506 40.377,32.175 41.527,31.025 v2@41.75,31.025 ; CN16.11@39.56,21.5 39.56,22.01 40.175,22.625 ; 40.177,22.623 43.803,26.249 43.803,28.978 v2@41.753,31.028 ; CN15.18@51.8,32.7 52.45,32.05 v2(52.45,31.25)
  other v2: 41.75,31.031
LCD-PSRAM_D8: CN15.19 CN16.10 U13.64 U14.B1 | length 92.6
  Top Layer w0.127: v2(16.826,39.901) 16.826,39.826 17.158,39.494 19.083,39.494 19.114,39.525 U13.64@20.2,39.525 ; U13.64@20.325,39.55 21.464,39.55 25.565,43.651 31.748,43.651 33.022,44.925 34.898,44.925 34.918,44.905 v2@34.975,44.905 ; U14.B1@22.475,25.925 22.475,27.55 v2(22.7,27.775) ; v2@34.931,44.949 34.941,44.959 34.975,44.993 v2(34.975,44.925) ; v2(38.55,26.425) 38.719,26.594 40.958,26.594 41.431,27.067 41.431,28.2 41.902,28.671 53.921,28.671 55.162,29.912 55.175,29.925 v2(55.15,29.925)
  Bottom Layer w0.127: v2(16.826,39.901) 16.826,39.874 17.437,39.263 17.437,35.988 18.575,34.85 18.575,33.772 20.034,32.313 20.034,31.611 21.799,29.845 21.799,29.379 22.7,28.478 v2(22.7,27.775) ; v2(34.975,44.925) 35.675,44.225 35.675,40.925 35.424,40.674 35.424,37.831 36.393,36.862 36.393,31.849 38.169,30.073 38.169,28.434 38.712,27.891 38.712,26.587 v2(38.55,26.425) 38.525,26.425 38.295,26.195 38.295,25.055 37.357,24.118 ; 37.347,24.128 37.337,24.118 35.327,24.118 34.057,22.848 34.057,20.402 35.077,19.382 39.05,19.382 39.26,19.172 CN16.10@39.26,18.625 ; CN15.19@55.05,30.925 CN15.19@55.1,30.925 ; v2(55.15,29.925) CN15.19@55.15,30.95
LCD-PSRAM_D9: CN15.20 CN16.9 U13.65 U14.C1 | length 74.7
  Top Layer w0.127: v2(16.9,39.1) 16.95,39.05 U13.65@20.2,39.05 ; U13.65@20.325,39.05 21.503,39.05 25.723,43.27 31.906,43.27 32.992,44.356 34.979,44.356 34.988,44.365 35.535,44.365 35.948,43.952 36.877,43.952 v2(36.877,43.977) ; U14.C1@21.725,25.925 21.725,26.95 v2(21.826,27.051) ; v2(42.177,30.051) 42.15,30.024 42.36,29.814 48.375,29.814 48.911,30.35 49.475,30.35 49.95,29.875 50.076,29.875 v2(50.077,29.876)
  Bottom Layer w0.127: v2(16.9,39.1) 17.056,38.944 17.056,34.752 19.653,32.155 19.653,31.453 21.418,29.687 21.418,29.221 22.246,28.392 22.246,27.514 21.826,27.094 v2(21.826,27.051) ; v2(36.877,43.977) 36.877,43.923 37.731,43.069 37.731,41.608 38.206,41.133 38.206,38.821 39.06,37.967 39.06,36.285 39.996,35.348 39.996,32.017 41.964,30.05 v2@42.171,30.05 ; CN16.9@38.96,21.5 38.96,21.949 42.531,25.519 ; v2@42.171,30.071 42.184,30.058 43.422,28.82 43.422,26.407 42.532,25.518 ; CN15.20@50.075,31.025 50.054,31.004 50.054,31 50.054,29.9 v2(50.077,29.876)
LCD-PSRAM_D10: CN15.21 CN16.8 U13.66 U14.C2 | length 93.8
  Top Layer w0.127: v2(15.825,38.95) 16.25,38.95 16.65,38.55 U13.66@20.15,38.55 ; U13.66@20.325,38.55 21.541,38.55 25.88,42.889 32.063,42.889 33.149,43.975 v2(35.15,43.975) ; v2(21.325,25.575) U14.C2@21.725,25.175 ; v2(37.525,27.35) 37.9,26.975 40.8,26.975 41.05,27.225 41.05,28.55 41.553,29.052 53.278,29.052 v2(54.05,29.825)
  Bottom Layer w0.127: v2(15.825,38.95) 16.35,38.95 16.675,38.625 16.675,34.594 19.272,31.998 19.272,31.295 21.037,29.529 21.037,29.063 21.865,28.235 21.865,27.672 21.325,27.131 v2(21.325,25.575) ; v2(35.15,43.975) 34.8,43.975 34.281,43.456 34.281,37.358 35.24,36.398 35.24,31.385 37.026,29.6 37.026,27.899 37.525,27.4 v2(37.525,27.35) ; v2@37.525,27.325 37.125,26.925 36.475,26.925 32.914,23.364 32.914,19.928 35.442,17.4 37.914,17.4 38.65,18.136 38.65,18.615 CN16.8@38.66,18.625 ; CN15.21@54.05,29 v2(54.05,29.825)
LCD-PSRAM_D11: CN15.22 CN16.7 U13.67 U14.D2 | length 74.2
  Top Layer w0.127: v2@16.3,38.275 16.406,38.169 19.156,38.169 19.275,38.05 U13.67@20.325,38.05 ; U13.67@20.35,38.05 U13.67@20.325,38.05 ; v2(20.576,24.801) 20.601,24.801 U14.D2@20.975,25.175 ; 35.013,43.438 35.275,43.175 v2(36.95,43.175) ; 35.025,43.45 34.897,43.577 33.291,43.577 32.221,42.508 26.038,42.508 21.58,38.05 U13.67@20.325,38.05 ; v2(41.5,29.575) 41.642,29.433 48.825,29.433 49.271,29.879 49.275,29.883 v2(49.275,29.875)
  Bottom Layer w0.127: v2(16.276,38.276) 16.25,38.251 16.25,34.48 18.891,31.84 18.891,31.137 20.656,29.372 20.656,26.848 20.575,26.767 v2@20.575,24.825 ; v2(36.95,43.175) 37.35,42.775 37.35,41.45 37.825,40.975 37.825,38.663 38.679,37.809 38.679,36.127 39.615,35.19 39.615,31.859 41.5,29.975 v2@41.5,29.6 ; CN16.7@38.36,21.5 38.36,21.888 43.041,26.568 43.041,28.035 v2(41.5,29.575) ; CN15.22@49.25,28.975 49.275,29 v2(49.275,29.875)
LCD-PSRAM_D12: CN15.23 CN16.6 U13.68 U14.E2 | length 88.3
  Top Layer w0.127: v2(15.701,37.726) 15.75,37.776 18.9,37.776 ; 18.9,37.775 19.125,37.55 U13.68@20.075,37.55 ; v2(19.875,25.525) U14.E2@20.225,25.175 ; U13.68@20.325,37.55 21.619,37.55 26.196,42.127 32.379,42.127 33.429,43.177 v2(34.677,43.177) ; v2(37.45,25.4) 37.95,24.9 53.075,24.9 v2(54.2,26.025)
  Bottom Layer w0.127: v2(15.701,37.726) 15.825,37.602 15.825,34.366 18.51,31.682 18.51,30.979 20.275,29.214 20.275,27.006 19.875,26.606 v2(19.875,25.525) ; v2(34.677,43.177) 34.731,43.177 34.704,43.15 34.662,43.109 34.662,37.516 35.631,36.547 35.631,31.533 37.407,29.757 37.407,28.118 37.95,27.575 37.95,27.05 37.45,26.55 v2(37.45,25.4) 37.056,25.006 35.137,25.006 33.295,23.164 33.295,20.086 35.631,17.75 37.725,17.75 38.05,18.075 38.05,18.615 CN16.6@38.06,18.625 ; CN15.23@54.175,26.975 54.2,26.95 v2(54.2,26.025)
LCD-PSRAM_D13: CN15.24 CN16.5 U13.77 U14.F2 | length 68.6
  Top Layer w0.127: v2(15.7,31.375) 16.09,31.765 21.911,31.765 22.353,32.208 23.765,32.208 24.2,32.643 U13.77@24.2,33.675 24.2,37.375 26.6,39.775 32.2,39.775 34.032,41.607 35.074,41.607 35.931,40.75 v2(37.4,40.75) ; v2(16.875,28.025) 17.164,28.025 19.106,26.083 19.106,25.544 U14.F2@19.475,25.175 ; v2(42.65,27.425) 47.975,27.425 49.312,26.087 v2@49.325,26.075
  Bottom Layer w0.127: v2(15.7,31.375) 16.575,30.5 16.575,28.325 v2(16.875,28.025) ; v2(37.4,40.75) 37.4,38.549 38.298,37.651 38.298,32.638 40.862,30.074 40.862,29.488 40.975,29.375 42.65,27.7 v2(42.65,27.425) 42.65,26.716 37.76,21.826 CN16.5@37.76,21.5 ; v2(49.3,26.075) 49.3,26.9 CN15.24@49.375,26.975
LCD-PSRAM_D14: CN15.25 CN16.4 U13.78 U14.F1 | length 81.4
  Top Layer w0.127: v2(16.45,31.375) 16.55,31.275 21.959,31.275 22.545,31.861 24.274,31.861 24.7,32.287 U13.78@24.7,33.675 24.7,33.975 24.7,37.336 26.758,39.394 32.358,39.394 34.014,41.05 35.075,41.05 v2(35.077,41.052) ; v2(17.15,29.1) 17.15,28.6 19.475,26.275 U14.F1@19.475,25.925 ; v2(37.025,24.6) 37.337,24.288 ; 37.35,24.3 53.775,24.3 v2(54.2,23.875)
  Bottom Layer w0.127: v2(16.45,31.375) 16.986,30.839 16.986,29.264 v2(17.15,29.1) ; v2(35.077,41.052) 35.043,41.018 35.043,37.673 36.012,36.704 36.012,31.691 37.788,29.915 37.788,28.276 38.331,27.733 38.331,26.892 37.913,26.474 37.913,25.212 37.301,24.6 v2@37.05,24.6 ; v2@37.025,24.625 35.295,24.625 33.676,23.006 33.676,20.244 35.823,18.097 37.372,18.097 37.46,18.185 CN16.4@37.46,18.625 ; v2(54.2,23.875) CN15.25@54.2,25
LCD-PSRAM_D15: CN15.26 CN16.3 U13.79 U14.G1 | length 70.8
  Top Layer w0.127: v2(15.25,30.775) 15.4,30.925 22.148,30.925 22.736,31.514 24.811,31.514 25.2,31.903 U13.79@25.2,33.675 U13.79@25.2,33.85 ; v2(16.675,27.35) 17.3,27.35 U14.G1@18.725,25.925 ; U13.79@25.225,33.85 25.225,37.322 26.916,39.013 32.516,39.013 33.478,39.975 v2(36.975,39.975) ; v2(37.175,22.525) 37.225,22.525 38.525,23.825 v2(49.275,23.825)
  Bottom Layer w0.127: v2(15.25,30.775) v2@15.25,30.8 ; v2(16.675,27.35) 16.147,27.878 16.147,29.903 15.262,30.788 v2@15.25,30.8 ; v2(36.975,39.975) 36.975,38.436 37.917,37.494 37.917,32.48 40.481,29.916 40.481,25.086 37.92,22.525 v2(37.175,22.525) v2@37.187,22.537 ; CN16.3@37.175,21.5 v2@37.175,22.5 ; CN15.26@49.2,24.7 49.275,24.625 v2(49.275,23.825) ; v2@15.25,30.8 15.215,30.835 15.25,30.87 v2@15.25,30.8
LCD-PSRAM_NOE: CN15.6 CN16.19 U13.118 U14.A2 | length 82.2
  Top Layer w0.127: U14.A2@23.225,25.175 25.326,27.276 v2(26.726,27.276) ; v2(27.55,45.625) 27.613,45.688 31.091,45.688 32.396,46.993 36.091,46.993 39.344,43.74 39.344,41.181 40.325,40.2 v2@40.325,40.05 ; v2(40.334,40.034) 41.084,40.034 U13.118@41.1,40.05 ; U13.118@41.125,40.075 U13.118@41.1,40.05 ; U13.118@41.45,40.05 U13.118@41.1,40.05 ; U13.118@41.575,40.05 44.076,40.05 44.704,40.678 45.269,40.678 45.847,41.256 45.847,42.106 46.469,42.728 49.181,42.728 50.484,41.425 v2(52.725,41.425)
  Bottom Layer w0.127: v2(26.726,27.276) 27.2,27.75 27.2,29.561 28.581,30.942 28.581,33.114 27.576,34.119 27.576,45.599 v2(27.55,45.625) ; v2(40.334,40.034) 40.316,40.034 40.316,38.866 40.584,38.598 40.584,36.916 42,35.5 42,33.791 43.493,32.298 43.493,31.443 45.327,29.61 45.327,25.618 41.96,22.252 CN16.19@41.96,21.5 ; CN15.6@51.575,44.925 52.725,43.775 v2(52.725,41.425)
LCD-PSRAM_NWE: CN15.3 CN16.20 R61.1 U13.119 | length 106.2
  Top Layer w0.127: v2(16,21.1) 16.75,21.1 17.225,20.625 R61.1@17.225,20.175 ; v2@26,45.7 26.6,45.7 26.969,46.069 30.933,46.069 32.204,47.34 36.282,47.34 39.725,43.897 39.725,42.425 v2@40.375,41.775 ; v2(40.4,41.75) 40.4,40.85 40.7,40.55 U13.119@41.575,40.55 41.575,40.431 43.919,40.431 44.513,41.025 45.125,41.025 45.5,41.4 45.5,42.25 46.325,43.075 49.325,43.075 50.2,42.2 v2(53.2,42.2)
  Bottom Layer w0.127: v2(16,21.1) 22.975,21.1 24.082,22.207 24.082,23.986 24.417,24.32 24.417,25.168 25.837,26.588 25.837,31.437 26.433,32.033 26.433,44.989 25.975,45.447 v2(25.975,45.7) ; v2(40.4,41.75) 40.4,41.473 41.6,40.273 41.6,37.337 44.856,34.081 44.856,33.169 46.724,31.301 46.724,24.74 48.65,22.814 48.65,20.586 48.008,19.944 42.883,19.944 42.26,19.321 CN16.20@42.26,18.625 ; v2(53.2,42.2) 53.2,46.1 CN15.3@53.875,46.775
LCD-RS_A0: CN15.1 CN16.21 R46.2 | length 84.1
  Top Layer w0.127: R46.2@33,58.5 33,60.6 33.9,61.5 38.4,61.5 v1@38.875,61.025 ; v1@38.8,60.875 39.425,61.5 55.8,61.5 v1(56.275,61.025)
  Bottom Layer w0.127: v1@38.875,60.925 38.275,60.325 38.275,57.425 39.125,56.575 39.125,55.1 38.075,54.05 38.075,48.894 37.86,48.678 37.86,47.066 39.756,45.17 39.756,41.219 40.965,40.01 40.965,37.074 42.381,35.658 42.381,33.949 44.175,32.155 44.175,31.5 ; CN16.21@42.56,21.5 42.56,22.313 45.708,25.46 45.708,29.967 44.2,31.475 ; CN15.1@55.1,49 55.35,49.25 55.35,50.425 56.275,51.35 v1(56.275,61.025)
  other v1: 38.875,60.95
LCD_BL_CTRL: CN15.2 L2.1 U13.4 | length 56.1
  Top Layer w0.127: U13.4@38.2,54.925 38.2,53.875 38.4,53.675 39.984,53.675 40.404,54.095 40.404,54.388 42.558,56.542 46.221,56.542 46.236,56.527 47.064,56.527 47.9,57.363 49.987,57.363 v1(50.45,56.9) ; v1(50.475,50.175) 50.5,50.2 v1(65.7,50.2) ; v1@67.787,38.612 v1(67.8,38.625)
  Top Layer w0.2: v1(67.5,35.05) 67.5,38.3 v1@67.8,38.6
  Bottom Layer w0.127: CN15.2@50.45,48.875 50.475,48.9 v1(50.475,50.175) 50.475,56.875 v1(50.45,56.9) ; v1(65.7,50.2) 66.121,49.779 66.121,48.646 65.825,48.35 65.825,40.625 v1@67.825,38.625
  Bottom Layer w0.4: L2.1@66.4,35.05 v1(67.5,35.05)
LCD_NE3: CN15.5 CN16.22 R105.2 U13.125 | length 52.6
  Top Layer w0.127: U13.125@41.575,43.55 42.5,43.55 ; 42.5,43.575 42.95,44.025 v1@42.95,44.175 ; v1@42.925,44.2 v1@42.95,44.175 ; v1@55.8,44 55.004,44.796 43.546,44.796 v1(42.95,44.2) v1@42.95,44.175
  Bottom Layer w0.127: CN16.22@42.86,18.625 42.86,19.16 43.297,19.597 48.397,19.597 49.031,20.231 49.031,22.972 47.105,24.898 47.105,31.459 45.237,33.327 45.237,34.239 43.925,35.551 43.925,39.737 45.44,41.253 45.44,41.753 42.994,44.2 v1(42.95,44.2) ; CN15.5@55.2,45.2 55.775,44.625 v1(55.775,44)
  Bottom Layer w0.2: R105.2@42.85,17.6 CN16.22@42.85,18.65
LCD_TE: CN15.13 CN16.2 U13.75 | length 71.3
  Top Layer w0.127: U13.75@23.2,33.675 23.2,37.273 26.752,40.825 v1(32.05,40.825) 32.209,40.984 32.852,40.984 33.856,41.988 35.232,41.988 35.76,41.46 37.369,41.46 37.627,41.202 ; v1(32.825,24.075) 32.825,21.35 35.55,18.625 v1(36.25,18.625) ; 37.625,41.2 38.856,39.969 38.856,36.922 40.676,35.101 49.388,35.101 49.918,35.632 ; 49.912,35.638 51.23,36.956 53.044,36.956 v1(54.025,35.975)
  Bottom Layer w0.127: v1(32.05,40.825) 32.312,40.564 32.312,38.212 31.775,37.675 31.775,34.125 31.362,33.712 31.362,29.809 29.987,28.434 29.987,24.813 30.725,24.075 v1(32.825,24.075) ; v1(36.25,18.625) CN16.2@36.86,18.625 ; CN15.13@53.975,36.975 54.025,36.925 v1(54.025,35.975)
LDO_3V3: C6.2 SB1.1 U4.2 U4.4 | length 10.4
  Top Layer w0.3: U4.4@43.575,93.5 U4.4@43.575,93.625 ; U4.2@43.575,99.85 43.575,99.6 U4.2@43.6,99.575 ; 45.325,101.775 45.35,101.75 45.425,101.825 SB1.1@45.425,102
  Top Layer w0.7: C6.2@43.575,101.775 45.325,101.775
  Top Layer w0.9: U4.4@43.575,93.5 U4.4@43.6,93.475 ; U4.4@43.575,93.625 U4.2@43.575,99.6 ; U4.2@43.575,99.85 C6.2@43.575,101.775
LED1_RED: R94.2 U13.2 | length 31.4
  Top Layer w0.127: U13.2@39.2,54.925 39.2,54.075 39.346,53.929 39.879,53.929 40.15,54.2 40.15,54.493 42.453,56.796 46.326,56.796 46.342,56.781 46.958,56.781 47.795,57.617 55.899,57.617 58.266,55.25 62.65,55.25 63.25,55.85 63.25,56.7 64.375,57.825 v1(64.375,58.175)
  Bottom Layer w0.127: v1(64.375,58.175) R94.2@65.05,58.175
LED2_GREEN: R93.1 U13.45 | length 56.4
  Top Layer w0.127: U13.45@20.325,49.05 21.9,49.05 22.075,48.875 23.591,48.875 23.945,48.521 30.455,48.521 31.005,49.071 39.121,49.071 v1(39.25,49.2) ; v1(42.975,60.175) 43.925,61.125 55.071,61.125 55.8,60.396 59.755,60.396 60.709,61.35 v1(64.475,61.35)
  Bottom Layer w0.127: v1(39.25,49.2) 39.975,49.925 39.975,53.4 42.975,56.4 v1(42.975,60.175) ; v1(64.475,61.35) 65.05,60.775 R93.1@65.05,59.675
LED_STLINK: R34.2 R38.2 U6.30 | length 36.4
  Top Layer w0.127: U6.30@50.825,89.45 50.825,87.432 v1(50.827,87.429) ; v1(51.949,69.049) 59.951,69.049 61.5,67.5 v1(64.125,67.5)
  Top Layer w0.2: v1(64.125,67.5) R34.2@65.275,67.5 R38.2@65.275,66
  Mid-Layer 1 w0.127: v1@50.779,87.429 v1(50.827,87.429)
  Bottom Layer w0.127: v1@50.8,87.425 50.8,79.6 51.949,78.451 v1(51.949,69.049)
LEDA: CN16.28 L3.2 | length 29.7
  Top Layer w0.4: v1(54.95,22.75) 54.95,22.775 56.025,23.85 56.025,29.3 57.75,31.025 59.75,31.025 62.05,33.325 v1@62.975,33.325
  Bottom Layer w0.127: v1(62.975,33.35) v1@63,33.375
  Bottom Layer w0.4: CN16.28@44.66,18.625 52.325,18.625 53.65,19.95 53.65,21.45 v1(54.95,22.75) ; v1@63,33.375 63.4,33.775 L3.2@63.4,34.4
LEDK: CN16.29 R101.2 U18.4 | length 25.2
  Top Layer w0.4: v1@46.375,22.6 49.513,22.6 49.915,22.198 53.427,22.198 55.55,20.075 60.1,20.075 61.775,21.75 61.775,23.85 60.775,24.85 v1(60.75,24.85)
  Bottom Layer w0.2: R101.2@61.7,25.25 R101.2@61.7,25.3 R101.2@61.725,25.3
  Bottom Layer w0.3: CN16.29@44.96,21.5 44.96,22.185 45.375,22.6 46.275,22.6 v1(46.3,22.575)
  Bottom Layer w0.4: v1(60.75,24.85) 61.15,25.25 R101.2@61.65,25.25 ; R101.2@61.825,25.6 62.325,26.1 U18.4@62.325,26.6
MCO: R7.1 U6.29 | length 1.4
  Top Layer w0.127: R7.1@51.275,90.8 51.325,90.75 U6.29@51.325,89.45
MEMS_LED: CN12.12 U13.3 | length 46.4
  Top Layer w0.127: CN12.12@4.96,66.61 8.616,62.954 11.38,62.954 13.463,60.871 16.88,60.871 17.255,61.246 19.843,61.246 20.834,62.237 23.737,62.237 26.225,64.725 28.531,64.725 28.576,64.681 35.713,64.681 36.444,63.95 v1(37.275,63.95) ; v1(38.402,56.328) 38.424,56.35 38.5,56.35 38.7,56.15 U13.3@38.7,54.925
  Bottom Layer w0.127: v1(37.275,63.95) 37.275,64 38.021,63.254 38.021,56.709 v1(38.402,56.328)
MIC_IN: C34.1 CN5.2 R39.2 | length 38.2
  Top Layer w0.25: CN5.2@1.25,76.2 1.25,76.725 2.45,77.925 5.325,77.925 5.9,77.35 6.95,77.35 7.6,78 14.25,78 16.15,76.1 v1(21.625,76.1) ; R39.2@20.225,64 C34.1@21.525,64 ; C34.1@21.5,64 C34.1@21.525,64 ; v1(22.675,64.025) 22.65,64 C34.1@21.525,64
  Bottom Layer w0.25: v1(21.625,76.1) 21.625,72.05 22.575,71.1 22.575,69.325 23.3,68.6 23.3,64.65 v1(22.675,64.025)
NetB1_3: B1.3 B1.4 C90.2 R106.2 R109.2 | length 21.1
  Bottom Layer w0.3: B1.4@58.55,11.175 63.6,11.175 64.2,11.775 64.2,11.825 ; R109.2@65.6,9.025 C90.2@66.6,9.025 66.6,10.525 B1.3@66.6,11.175 ; B1.3@67.45,11.175 B1.3@66.6,11.175 ; R106.2@67.875,17.35 65.45,17.35 64.2,16.1 64.2,11.825 ; 64.2,11.825 64.85,11.175 B1.3@66.6,11.175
